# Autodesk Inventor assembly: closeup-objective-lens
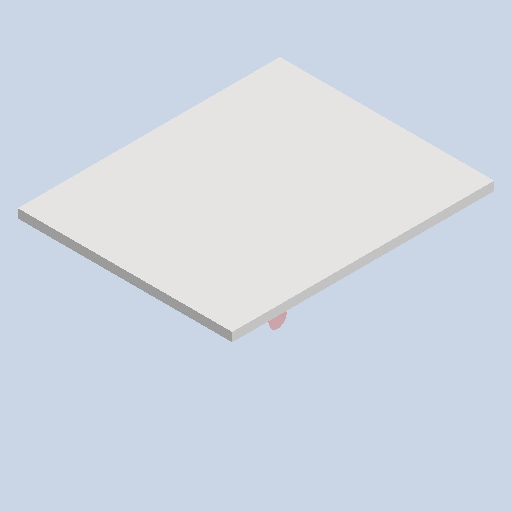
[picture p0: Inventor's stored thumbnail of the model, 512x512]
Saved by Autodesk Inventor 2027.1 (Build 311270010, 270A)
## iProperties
Created: 2026-08
Part Number: closeup-objective-lens
Document SubType Name: Assembly
Designer: dunge
Author: dunge
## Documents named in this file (3)
- C:\Users\dunge\OneDrive\Documents\Inventor\Inventor\Inventor\simplified-drawings\closeup-objective-lens.iam
- C:\Users\dunge\OneDrive\Documents\Inventor\Inventor\Inventor\simplified-drawings\imports\N16XLWD-PF-Solidworks\N16XLWD-PF-Solidworks.ipt
- C:\Users\dunge\OneDrive\Documents\Inventor\Inventor\Inventor\simplified-drawings\renders\closeup-objective-lens-light-paths.ipt
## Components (2 placed, 2 different names)
1. N16XLWD-PF-Solidworks:1
2. closeup-objective-lens-light-paths:1
## Named parameters: Finish1_Area = 564.77541 mm, Finish2_Area = 264.06415 mm, Finish3_Area = 45899.7332 mm
